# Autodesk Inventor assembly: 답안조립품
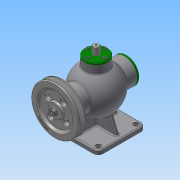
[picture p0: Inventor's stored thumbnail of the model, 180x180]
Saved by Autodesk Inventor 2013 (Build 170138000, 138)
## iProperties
Created: 2018-06
Part Number: 답안조립품
Document SubType Name: Assembly
Designer: Administrator
Author: Administrator
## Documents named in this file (19)
- C:\Users\Administrator\Desktop\480612V1011\답안조립품.iam
- C:\Users\Administrator\Desktop\480612V1011\본체.ipt
- C:\Users\Administrator\Desktop\480612V1011\V-벨트풀리.ipt
- C:\Users\Administrator\Desktop\480612V1011\너트 M8.ipt
- C:\Users\Administrator\Desktop\480612V1011\뒤커버.ipt
- C:\Users\Administrator\Desktop\480612V1011\멈춤링 15x1.ipt
- C:\Users\Administrator\Desktop\480612V1011\멈춤링 35x1.6.ipt
- 멈춤링 35x1.6.ipt
- C:\Users\Administrator\Desktop\480612V1011\베어링 6202.ipt
- 베어링 6202.ipt
- C:\Users\Administrator\Desktop\480612V1011\볼트 M4x12.ipt
- C:\Users\Administrator\Desktop\480612V1011\볼트 M4x16.ipt
- C:\Users\Administrator\Desktop\480612V1011\부시.ipt
- C:\Users\Administrator\Desktop\480612V1011\상부커버.ipt
- C:\Users\Administrator\Desktop\480612V1011\슬라이드.ipt
- C:\Users\Administrator\Desktop\480612V1011\앞커버.ipt
- C:\Users\Administrator\Desktop\480612V1011\오일 실 15 30 7.ipt
- C:\Users\Administrator\Desktop\480612V1011\키 4x4x12.ipt
- C:\Users\Administrator\Desktop\480612V1011\편심축.ipt
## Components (1 placed, 1 different names)
1. V-벨트풀리:1
